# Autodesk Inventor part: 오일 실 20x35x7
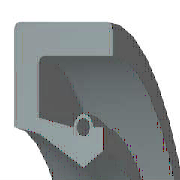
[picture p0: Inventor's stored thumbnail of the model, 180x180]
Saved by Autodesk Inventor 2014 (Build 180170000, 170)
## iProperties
IsCustomPart: 1
Created: 2012-02
Part Number: 오일 실 20x35x7
Material: 고무
Description: 회전 샤프트 립 유형 실 2 - 금속 케이스
Document SubType Name: Modeling
Standard: ISO 6194/1
Designer: mduedu
Standards Organization: ISO
Language: ko-KR
Size Designation: 20x35x7-유형 2
Categories: <MemberInstance><Categories><Category DisplayName="샤프트 부품" InternalName="7f7aeb1f-a693-4053-b835-cee3144e0d98" Mnemonic="SHFT"><Category DisplayName="실링" Intern
Density: 0.93 g/cm^3
Appearance: Rubber - Black - Version 1.1
Author: mduedu
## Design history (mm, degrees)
node "WorkPlane2"
node "WorkPoint1"
node "WorkPlane3"
body "Solid1"
node "스케치1"
revolve "회전1" stored, may be unused: angle "d37" = 360 deg
fillet "모깎기1" dims "d38" = 0.35 (= 0.05 x b)
sketch "스케치2"
  geometry: L1 (16, -0.35)-(16.8, -0.35); L2 (16, 0)-(16, -0.35); L3 (17.5, 0)-(16, 0); L4 (17.5, -7)-(17.5, 0); L5 (12.22, -7)-(17.5, -7); L6 (11.283, -4.2)-(12.22, -7); L7 (10.601, -3.72)-(11.283, -4.2); L8 (10, -1.925)-(10.601, -3.72); L9 (10.789, -1.05)-(10, -1.925); L10 (12.664, -1.05)-(10.789, -1.05); L11 (12.664, -1.925)-(12.664, -1.05); L12 (12.664, -5.6)-(12.664, -3.325); L13 (13.664, -5.6)-(12.664, -5.6); L14 (13.664, -6.3)-(13.664, -5.6); L15 (16.8, -6.3)-(13.664, -6.3); L16 (16.8, -0.35)-(16.8, -6.3); L17 (0, -15.959)-(0, 2.029); L18 (0, -15.959)-(0, 2.029); L19 (0, -19.557)-(0, 5.626) reference; L20 (-5.2, 0)-(31.2, 0) reference; A1 r 0.7 centre (12.664, -2.625) between (12.664, -3.325) and (12.664, -1.925)
  constraints: 36 end point, 7 vertical, 6 horizontal, 2 collinear, 2 point on circle, 1 centre point, 1 parallel, 1 point on line
  dimensions: "d2" = 0.35 distance of L2.start L1.start (= 0.05 x b); "d4" = 7 distance of L4.start L3.start (= b); "d6" = 0.7 horizontal distance of L1.end L3.start (= 0.1 x b); "d8" = 0.7 horizontal distance of L15.start L4.start (= 0.1 x b); "d10" = 0.7 distance of L14.start L13.start (= 0.1 x b); "d12" = 0.7 vertical distance of L1.end L10.start (= 0.1 x b); "d14" = 0.875 distance of L11.start L10.start (= 0.125 x b); "d16" = 0.7 radius of A1 (= 0.1 x b); "d18" = 0 horizontal distance of A1.centre L12.end; "d20" = 0.875 vertical distance of L9.start L8.start (= 0.125 x b); "d22" = 1.79487 vertical distance of L8.start L7.start (= 0.25641 x b); "d24" = 2.8 vertical distance of L6.start L5.start (= 0.4 x b); "d26" = 1.5 distance of L3.start L2.start (= 0.1 x dd - 0.1 x Diam); "d28" = 0.78947 horizontal distance of L9.start L8.start (= 0.0526316 x dd - 0.0526316 x Diam); "d30" = 1.875 distance of L10.start L9.start (= 0.125 x dd - 0.125 x Diam); "d32" = 1 distance of L13.start L12.start (= 0.0666667 x dd - 0.0666667 x Diam); "d34" = 0.9375 horizontal distance of L6.start L5.start (= 0.0625 x dd - 0.0625 x Diam); "d36" = 0.68182 horizontal distance of L7.start L6.start (= 0.0454545 x dd - 0.0454545 x Diam); "msp_d39" = 20 diameter of L8.start L17 (= Diam); "msp_d40" = 35 diameter of L4 L17 (= dd)
other parameters: "dd" = 35 [user parameter; used in 7 equation terms], "Diam" = 20 [user parameter; used in 7 equation terms], "b" = 7 [user parameter; used in 13 equation terms], "d0" = -7 (computed from b), "d1" = 0.4 (derived), "d3" = 8 (derived), "d5" = 0.8 (derived), "d7" = 0.8 (derived), "d9" = 0.8 (derived), "d11" = 0.8 (derived), "d13" = 1 (derived), "d15" = 0.8 (derived), "d17" = 0 (derived), "d19" = 1 (derived), "d21" = 2.05128 (derived), "d23" = 3.2 (derived), "d25" = 2 (derived), "d27" = 1.05263 (derived), "d29" = 2.5 (derived), "d31" = 1.33333 (derived), "d33" = 1.25 (derived), "d35" = 0.90909 (derived), "d42" = 0
